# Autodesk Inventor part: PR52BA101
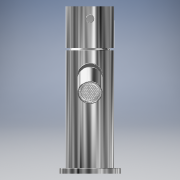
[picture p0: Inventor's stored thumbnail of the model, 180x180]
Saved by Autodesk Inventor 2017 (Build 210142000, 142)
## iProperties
Created: 2021-04
Part Number: PR52BA101
Material: Generico
Document SubType Name: Modeling
Designer: PIZZERA
Density: 1 g/cm^3
Appearance: Default
Author: PIZZERA
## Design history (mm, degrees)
feature "Base4"
node "Solido1"
node "Solido5"
